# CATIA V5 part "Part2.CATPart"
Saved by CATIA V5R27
Part number: Part2.2
Bounding box of the stored display mesh (mm): x -50.25 to 50.25, y 0 to 2, z -50.25 to 50.25
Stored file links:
  E:\university\my-thesis\My Thesis Publication\Final-Updata\CAD\Part2.CATPart
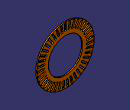
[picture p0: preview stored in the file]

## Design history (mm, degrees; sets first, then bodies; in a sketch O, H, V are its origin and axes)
Set1
  Sketch1 on zx-plane, origin (0, 0, 0), H (-1, 0, 0), V (0, 0, 1)
    circle A1 centre (0, 0) radius 30.25
    circle A2 centre (0, 0) radius 50.25
    radius A1 = 30.25
    distance A1 A2 = 20
    concentricity: A1 A2
  Sketch2 on end face of Pad1, origin (0, 2, 0), H (-1, 0, 0), V (0, 0, 1)
    construction line L1 (0, 47.75) -> (0, 37.75)
    point P1 (0, 47.75)
    line L2 (1.5, 47.75) -> (1.5, 37.75)
    line L3 (-1.5, 37.75) -> (-1.5, 47.75)
    arc A1 centre (0, 37.75) radius 1.5 from (1.5, 37.75) to (-1.5, 37.75) cw
    arc A2 centre (0, 47.75) radius 1.5 from (-1.5, 47.75) to (1.5, 47.75) cw
    distance L1 L2 = 1.5
    length L1 = 10
    distance P1 H = 47.75
    coincidence: P1 V
    vertical: L1 V
    tangency: A1 L2, A2 L2, A1 L3, A2 L3
Body1 (main body)
  Pad1: profile Sketch1, direction (0, 1, 0), length 2
  Pocket1: profile Sketch2, direction (0, -1, 0), length 2
  CircPattern1: of Pocket1, instances 40, angular step 9.2308, axis from end face of Pad1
